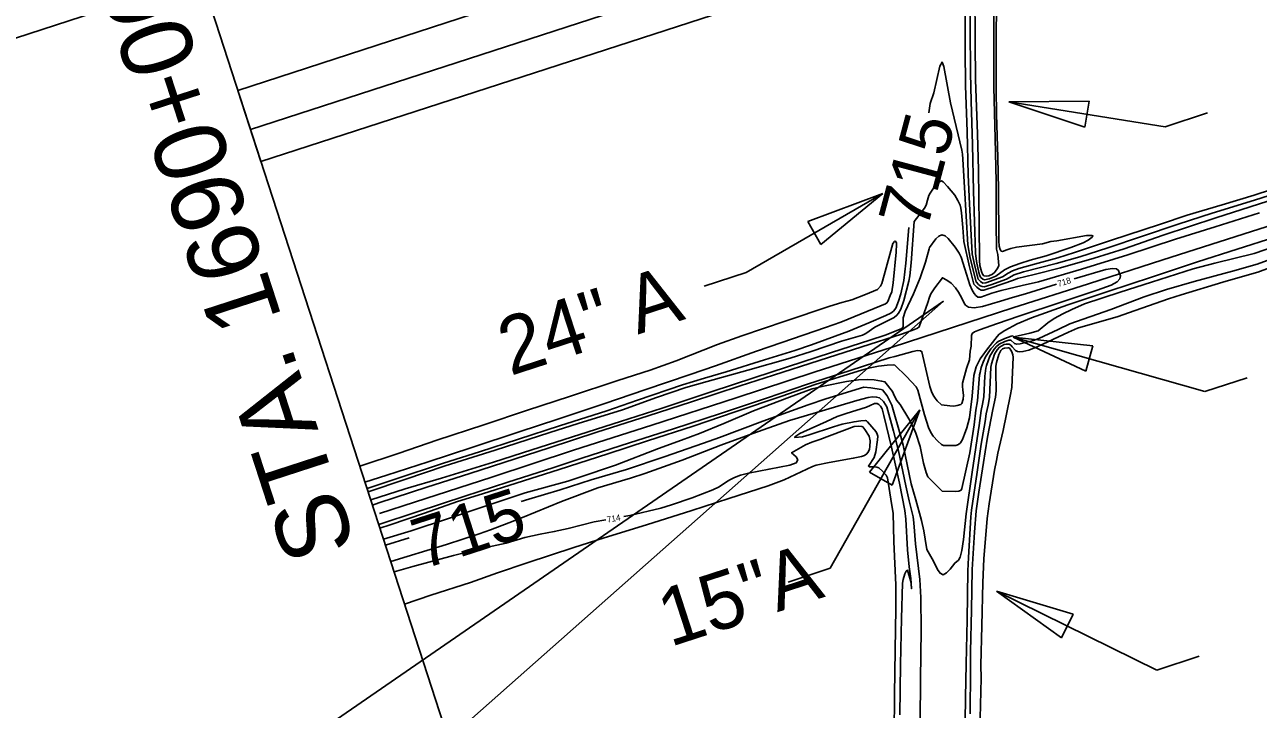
# Model space of a CAD drawing. Extents: x -468548933 to 3387700, y -306089263 to 1207014.
# Drawn here: x 1834585 to 1835390, y 535108 to 535554 of the extents above; entities that cross this region are included whole.
import ezdxf

# ---------------------------------------------------------------- set-up
doc = ezdxf.new("R2010")
doc.units = 0
for name, color, linetype in [('Default', 7, 'Continuous'), ('DT_X_Contour_Minor', 7, 'Continuous'), ('DT_X_Terrain_Ground_Line', 7, 'Continuous'), ('Level 14', 7, 'Continuous'), ('Level 19', 7, 'Continuous'), ('Level 40', 7, 'Continuous'), ('SC_Scratch1', 7, 'Continuous'), ('SC_Shading3', 7, 'Continuous')]:
    doc.layers.add(name, color=color, linetype=linetype)

msp = doc.modelspace()

# ---------------------------------------------------------------- linework, layer by layer
at = {"layer": 'Default'}
msp.add_lwpolyline([(1834724.08, 535511.25), (1834732.34, 535485.8), (1835112.79, 535609.32), (1835104.4, 535635.1)], close=True, dxfattribs=at)
at = {"layer": 'DT_X_Contour_Minor'}
for points in [[(1835219.01, 535568.51), (1835218.9, 535543.58), (1835218.75, 535511.83), (1835218.97, 535495.85), (1835219.96, 535467.46), (1835220.45, 535446.81), (1835220.55, 535413.17), (1835220.76, 535409.75), (1835221.36, 535407.54), (1835222.22, 535406.38), (1835222.92, 535406.29), (1835225.88, 535407.26), (1835228.49, 535408.13), (1835232.02, 535408.94), (1835249.12, 535411.22), (1835254.51, 535412.65), (1835258.36, 535413.13), (1835277.87, 535416.68), (1835281.17, 535416.67), (1835281.95, 535416.31), (1835281.53, 535415.56), (1835278.84, 535413.63), (1835275.71, 535411.95), (1835267.61, 535408.91), (1835251.5, 535403.43), (1835241.01, 535400.45), (1835234.26, 535398.36), (1835228.23, 535396.16), (1835224.27, 535394.14), (1835218.66, 535390.05), (1835214.19, 535388.35), (1835211.34, 535387.78), (1835210.22, 535388.06), (1835208.88, 535389.35), (1835208.26, 535390.39), (1835207.63, 535392.52), (1835206.03, 535399.61), (1835205.4, 535405.19), (1835205, 535418.92), (1835204.1, 535445.46), (1835203.46, 535476.08), (1835202.52, 535504.27), (1835202.03, 535522.72), (1835201.83, 535551.87), (1835201.89, 535578.71)], [(1835217.29, 535561.21), (1835217.32, 535530.19), (1835217.42, 535513.34), (1835218.19, 535479.94), (1835218.86, 535451.94), (1835218.82, 535424.79), (1835219.03, 535407.75), (1835219.96, 535404.24), (1835220.56, 535396.99), (1835220, 535395.63), (1835218.01, 535392.76), (1835216.48, 535391.36), (1835213.99, 535390.35), (1835212.48, 535390.14), (1835210.9, 535390.33), (1835209.98, 535391.45), (1835209.25, 535393.23), (1835208.3, 535397.02), (1835207.95, 535400.23), (1835207.72, 535423.53), (1835207.22, 535459.27), (1835206.58, 535483.02), (1835205.4, 535518.24), (1835205.08, 535542.71), (1835205.02, 535576.5)], [(1835198.58, 535568.22), (1835198.63, 535537.99), (1835198.86, 535514.32), (1835199.85, 535484.42), (1835200.64, 535456.13), (1835201.44, 535437.36), (1835203.24, 535404.69), (1835204.93, 535396.56), (1835207.13, 535388.14), (1835208.52, 535386.62), (1835210.21, 535385.55), (1835212.05, 535385.73), (1835222.94, 535389.63), (1835226.58, 535392.09), (1835229.42, 535393.53), (1835233.74, 535395.1), (1835243.81, 535398.03), (1835259.14, 535402.11), (1835269.97, 535405.49), (1835293.54, 535413.41), (1835326.12, 535424.12), (1835343.47, 535429.86), (1835366.35, 535436.68), (1835387.12, 535443), (1835410.39, 535450.48)], [(1835174.84, 535496.73), (1835175.68, 535502.77), (1835178.16, 535509.64), (1835182.11, 535527.01), (1835183.57, 535529.77), (1835184.8, 535526.92), (1835188.98, 535503.14), (1835196.34, 535472.21), (1835196.84, 535469.63), (1835197.16, 535466.36), (1835198.22, 535447.9), (1835200.29, 535410.47), (1835201.95, 535401.95), (1835205.71, 535386.48), (1835207.32, 535384.76), (1835208.41, 535383.88), (1835209.65, 535383.31), (1835210.96, 535383.26), (1835215.29, 535384.57), (1835225.6, 535388.22), (1835230.61, 535390.9), (1835236.7, 535392.86), (1835257.91, 535398.28), (1835273.39, 535402.75), (1835291.63, 535408.55), (1835313.67, 535415.88), (1835337.62, 535424.06), (1835359.7, 535431.19), (1835387.5, 535439.71), (1835416.71, 535449.08)], [(1834809.06, 535249.49), (1834832.96, 535257.62), (1834859.33, 535266.4), (1834891.93, 535276.68), (1834927.57, 535288.16), (1834946.17, 535293.95), (1834974.98, 535302.96), (1834997.14, 535310.89), (1835016.36, 535317.57), (1835030.2, 535321.45), (1835056.78, 535328.78), (1835084.45, 535336.59), (1835098.16, 535341.03), (1835117.95, 535347.63), (1835131.68, 535351.67), (1835133.75, 535352.66), (1835139.69, 535356.81), (1835152.4, 535363.26), (1835154.08, 535364.58), (1835155.22, 535365.9), (1835156.62, 535368.59), (1835158.58, 535374.34), (1835161.93, 535386.88), (1835162.62, 535390.37), (1835163.43, 535398.9), (1835165.29, 535425.68), (1835172.02, 535434.35), (1835173.14, 535436.39), (1835174.11, 535439.61), (1835174.94, 535442.75), (1835175.68, 535444.33), (1835178.05, 535447.4), (1835181.95, 535451.73), (1835183.15, 535452.21), (1835184.34, 535451.7), (1835187.02, 535448.65), (1835191.82, 535442.89), (1835193.9, 535439.38), (1835195.26, 535436.35), (1835195.82, 535434.4), (1835196.3, 535431.35), (1835197.05, 535421.92), (1835197.75, 535412.79), (1835201.55, 535396.11), (1835204.29, 535384.83), (1835206.13, 535382.9), (1835207.5, 535381.8), (1835209.1, 535381.06), (1835210.77, 535381), (1835213.5, 535381.86), (1835215.53, 535382.58), (1835230.25, 535387.55), (1835232.7, 535388.57), (1835243.58, 535391.22), (1835260.83, 535395.63), (1835282.7, 535401.89), (1835302.35, 535407.94), (1835327.8, 535416.75), (1835362.19, 535428.21), (1835384.67, 535435.36), (1835413.63, 535444.65)], [(1835390.57, 535431.45), (1835361.82, 535422.18), (1835335.79, 535414.18), (1835304.83, 535403.93), (1835274.63, 535394.71), (1835246.5, 535386.47), (1835235.76, 535383.99), (1835222.22, 535380.87), (1835215.96, 535378.98), (1835208.88, 535376.41), (1835206.87, 535376.32), (1835205.6, 535377.59), (1835204.58, 535378.84), (1835203.24, 535380.94), (1835201.67, 535384.4), (1835198.31, 535394.95), (1835196.03, 535402.54), (1835194.74, 535405.17), (1835192.08, 535409.12), (1835187.43, 535414.58), (1835185.53, 535416.32), (1835183.49, 535417.06), (1835181.44, 535416.25), (1835179.58, 535414.48), (1835175.41, 535408.9), (1835175.06, 535407.86), (1835172.67, 535399.3), (1835169.24, 535389.06), (1835164.94, 535378.54), (1835159.53, 535367.04), (1835158.25, 535362.98), (1835158.12, 535357.34), (1835157.76, 535356.38), (1835156.92, 535355.77), (1835146.37, 535351.75), (1835136.34, 535348.35), (1835111.47, 535340.36), (1835082.77, 535330.99), (1835060.79, 535323.86), (1835032.85, 535314.69), (1835000.91, 535304.12), (1834973.67, 535295.36), (1834947.31, 535286.89), (1834915.9, 535276.82), (1834890.89, 535268.91), (1834857.05, 535258.46), (1834833.24, 535251.39), (1834810.73, 535244.36)], [(1834808.39, 535251.55), (1834826.82, 535257.66), (1834858.3, 535268.21), (1834881.72, 535275.65), (1834907.29, 535283.83), (1834933.87, 535292.49), (1834964.88, 535302.26), (1834984.92, 535309.18), (1835014.18, 535319.35), (1835028.57, 535323.66), (1835042.77, 535327.72), (1835067.65, 535335.6), (1835087.55, 535341.54), (1835098.3, 535345.25), (1835122.75, 535354.28), (1835135.8, 535359.63), (1835146.83, 535364.42), (1835150.09, 535366.06), (1835151.84, 535367.24), (1835153.32, 535369.22), (1835155.2, 535373.92), (1835156.68, 535378.67), (1835158.57, 535387.31), (1835159.99, 535398.68), (1835161.82, 535421.94)], [(1834803.62, 535266.23), (1834829.3, 535274.61), (1834853.83, 535283.13), (1834884.47, 535293.22), (1834913.15, 535302.72), (1834940.38, 535311.58), (1834972.06, 535321.99), (1834993.1, 535328.87), (1835010.02, 535334.89), (1835037.09, 535345.6), (1835052.91, 535351.29), (1835081.2, 535360.67), (1835110.22, 535370.6), (1835118.06, 535372.9), (1835124.64, 535374.72), (1835133.62, 535378.11), (1835141.42, 535381.45), (1835143.48, 535383.61), (1835144.3, 535385.27), (1835145.88, 535390.8), (1835151.48, 535411.41), (1835152.56, 535412.82), (1835152.96, 535412.97), (1835153.28, 535412.72), (1835153.74, 535411.63), (1835153.87, 535410.99), (1835153.57, 535405.8), (1835151.63, 535385.82), (1835150.75, 535379.81), (1835149.78, 535377.5), (1835148.08, 535373.63), (1835147.58, 535372.66), (1835146.54, 535372.07), (1835139.35, 535369.05), (1835117.52, 535360.11), (1835107.51, 535356.54), (1835079, 535346.82), (1835062.54, 535341.25), (1835035.67, 535331.59), (1835019.16, 535326.06), (1834989.72, 535316.09), (1834963.57, 535307.18), (1834932.89, 535296.97), (1834907.71, 535288.6), (1834876.75, 535278.43), (1834848.15, 535269.06), (1834821.32, 535260.3), (1834807, 535255.83)], [(1835400.58, 535415.58), (1835376, 535407.7), (1835350.29, 535399.36), (1835320.93, 535389.77), (1835291.63, 535380.1), (1835265.64, 535371.35), (1835241.82, 535363.05), (1835232.6, 535358.94), (1835224.53, 535354.66), (1835220.81, 535352.38), (1835219.49, 535350.83), (1835214.89, 535344.8), (1835213.78, 535343.59), (1835208.41, 535336.16), (1835205.81, 535330.91), (1835204.29, 535325.4), (1835203.2, 535311.85), (1835201.4, 535297.82), (1835199.64, 535291.26), (1835198.29, 535287.07), (1835196.85, 535283.52), (1835195.5, 535281.37), (1835194.34, 535280.37), (1835192.54, 535279.76), (1835184.56, 535279.74), (1835183.14, 535280.31), (1835180.83, 535282.43), (1835177.75, 535285.77), (1835176.14, 535288.22), (1835174.7, 535291.38), (1835172.12, 535299.69), (1835167.82, 535315.83), (1835166.73, 535317.98), (1835160.25, 535324.65), (1835152.82, 535332.11)], [(1835400.37, 535409.56), (1835387.21, 535404.9), (1835361.48, 535398.62), (1835347.31, 535394.97), (1835320.2, 535386.27)], [(1835409.93, 535405.65), (1835389.2, 535398), (1835373.06, 535393.42), (1835347.98, 535386.62), (1835329.96, 535381.48), (1835315.51, 535376.56), (1835293.72, 535368.45), (1835266.91, 535359.02), (1835259.2, 535355.32), (1835246.76, 535349.41), (1835243.31, 535348.21), (1835234.47, 535345.93), (1835232.37, 535345.68), (1835230.84, 535346.12), (1835228.52, 535348.47), (1835227.06, 535348.39), (1835224.47, 535347.59), (1835220.91, 535345.83), (1835219.11, 535344.26), (1835217.47, 535342.43), (1835214.67, 535337.93), (1835212.45, 535331.78), (1835212.15, 535330.09), (1835211.66, 535326.54), (1835211.49, 535324.98), (1835210.79, 535311.4), (1835209.94, 535306.73), (1835209.11, 535302.41), (1835207.81, 535292.83), (1835207.06, 535288.69), (1835203.22, 535262.32), (1835199.21, 535235.22), (1835197.43, 535218.42), (1835196.4, 535211.28), (1835195.27, 535206.98), (1835194.19, 535204.96), (1835191.79, 535202.99), (1835188.79, 535199.11), (1835186.48, 535196.66), (1835184.19, 535195.46), (1835182.26, 535196.41), (1835180.65, 535198.86), (1835177.91, 535204.3), (1835173.64, 535211.98), (1835172.49, 535218.58), (1835171.55, 535224.12), (1835170.18, 535230.68), (1835166.41, 535244.36), (1835163.3, 535254.79), (1835158.13, 535279.88), (1835156.7, 535285.53), (1835150.79, 535306.09), (1835147.83, 535312.02), (1835144.58, 535315.89), (1835143.79, 535316.2), (1835137.15, 535317.23), (1835132.4, 535317.68), (1835107.81, 535310.08), (1835096.2, 535306.28), (1835066.64, 535295.56), (1835038.36, 535284.94), (1835027.85, 535281.16), (1835002.24, 535272.4), (1834977.68, 535264.04), (1834954.59, 535257.21), (1834934.3, 535250.76), (1834913.87, 535244.68), (1834909.03, 535243.18)], [(1835416.55, 535402.64), (1835389.63, 535392.83), (1835376.63, 535388.98), (1835366.72, 535386.18), (1835339.49, 535378.01), (1835331.28, 535375.36), (1835305.1, 535366.17), (1835298.42, 535363.88), (1835271.94, 535356.16), (1835266.06, 535353.57), (1835246.09, 535344.19), (1835240.18, 535341.84), (1835236.35, 535340.95), (1835234.13, 535340.81), (1835232.74, 535340.99), (1835231.42, 535341.6), (1835229.34, 535344.08), (1835228.37, 535345.2), (1835227.33, 535345.77), (1835225.49, 535345.85), (1835224.13, 535345.48), (1835221.01, 535343.79), (1835219.41, 535342.13), (1835217.77, 535339.25), (1835215.83, 535333.01), (1835215.35, 535330.74), (1835214.55, 535311.02), (1835213.57, 535306.04), (1835212.35, 535300.37), (1835211.71, 535295.26), (1835209.14, 535280.46)], [(1835269.7, 535388.29), (1835290.49, 535394.41), (1835294.8, 535395.17), (1835297.42, 535394.91), (1835298.71, 535393.82), (1835299.16, 535392.54)], [(1834811.85, 535240.89), (1834815.99, 535242.25), (1834847.32, 535252.46), (1834875.42, 535261.54), (1834897.52, 535268.6), (1834927.16, 535278.25), (1834958.37, 535288.29), (1834991.82, 535299.02), (1835020.08, 535308.16), (1835051.86, 535318.55), (1835073.62, 535325.59), (1835103.43, 535335.22), (1835131.14, 535343.95), (1835157.15, 535352.34), (1835165.48, 535355.23), (1835167.61, 535356.2), (1835168.51, 535357.06), (1835174.26, 535373), (1835175.29, 535376.43), (1835176.22, 535378.51), (1835178.91, 535382.51), (1835183.74, 535389.04), (1835186.61, 535387.46), (1835189.38, 535385.45), (1835192.32, 535382.57), (1835194.28, 535379.64), (1835196.51, 535375.69), (1835197.99, 535372.55), (1835198.91, 535371.2), (1835200.83, 535369.93), (1835204.43, 535369.51), (1835210.01, 535370.44), (1835221.57, 535373.83), (1835229.4, 535376.19), (1835237.91, 535378.66), (1835258.21, 535384.81)], [(1835299.16, 535392.54), (1835299.93, 535390.42), (1835299.63, 535388.45), (1835297.75, 535386.39), (1835293.86, 535384.31), (1835284.85, 535380.97), (1835261.84, 535373.46), (1835233.57, 535364.08), (1835219.81, 535359.25), (1835207.87, 535355.1), (1835204.62, 535353.71), (1835203.22, 535352.63), (1835202.86, 535351.47), (1835202.58, 535344.51), (1835201.98, 535341.27), (1835201.46, 535335.51), (1835199.45, 535329.92), (1835196.99, 535320.25), (1835196.78, 535318.33), (1835197.01, 535315.84), (1835197.59, 535312.55), (1835197.22, 535309.82), (1835196.39, 535307), (1835195.81, 535306.42), (1835193.48, 535305.71), (1835191.21, 535305.39), (1835188.54, 535305.51), (1835183.24, 535306.2), (1835180.31, 535308.91), (1835179.01, 535310.49), (1835177.82, 535312.43), (1835176.72, 535314.91), (1835175.65, 535318.15), (1835173.57, 535326.59), (1835170.37, 535340.82), (1835169.5, 535341.43), (1835167.61, 535341.54), (1835164.48, 535340.91), (1835152.83, 535337.82), (1835148.96, 535336.84), (1835123.62, 535328.66), (1835095.77, 535319.59), (1835068.92, 535310.6), (1835038.9, 535300.6), (1835008.29, 535290.62), (1834979.56, 535281.36), (1834948.54, 535271.33), (1834929.48, 535265.19), (1834900.27, 535255.68), (1834872.09, 535246.65), (1834841.1, 535236.41), (1834815.96, 535228.23)], [(1835320.2, 535386.27), (1835299.78, 535379.69), (1835276.47, 535372.01), (1835268.27, 535368.36), (1835262.27, 535365.48), (1835256.68, 535362.48), (1835252.62, 535359.79), (1835246.19, 535354.46), (1835240.79, 535353.01), (1835230.43, 535350.57), (1835230, 535350.97), (1835229.7, 535351.18), (1835228.62, 535350.93), (1835224.44, 535349.53), (1835220.18, 535347.43), (1835219.17, 535346.54), (1835215.42, 535342.7), (1835211.92, 535337.62), (1835210.36, 535334.08), (1835208.98, 535330.5), (1835208.31, 535327.36), (1835207.92, 535325.7), (1835206.61, 535308.8), (1835205.66, 535302.81), (1835204.45, 535293.1), (1835201.64, 535274.91), (1835196.53, 535251.7), (1835195.96, 535250.64), (1835194.58, 535250.02), (1835191.99, 535249.66), (1835183.54, 535249.95), (1835174.2, 535259.37), (1835173.1, 535262.03), (1835171.5, 535268.14), (1835169.22, 535279.04), (1835166.44, 535287.84), (1835165.19, 535290.81), (1835161.8, 535297.1), (1835156.14, 535306.33), (1835153.81, 535309.27), (1835151.91, 535313.48), (1835151.19, 535314.85), (1835146.24, 535321.31), (1835144.12, 535321.68), (1835139.29, 535322.47), (1835135, 535322.75), (1835128.97, 535322.47), (1835121.21, 535321.39), (1835106.29, 535318.47), (1835098.71, 535316.6), (1835084, 535311.22), (1835060.53, 535302.39), (1835041.11, 535294.09), (1835025.39, 535287.62), (1835013.49, 535283.16), (1834998.5, 535277.82), (1834970.58, 535266.96), (1834946.61, 535258.75), (1834939.47, 535256.42), (1834911.55, 535248.75), (1834906.23, 535247.13), (1834882.82, 535239.16), (1834861.53, 535231.99), (1834837.19, 535224.15), (1834819.07, 535218.66)], [(1835201.8, 535104.78), (1835202.13, 535133.31), (1835202.02, 535145.37), (1835202.65, 535172.42), (1835203.09, 535198.9), (1835204.71, 535223.28), (1835205.75, 535237.06), (1835207.5, 535249.33), (1835210.67, 535268.69), (1835211.71, 535275.61), (1835213.1, 535285.06), (1835216.68, 535303.17), (1835218.4, 535311.19), (1835218.94, 535315.31), (1835218.66, 535328.02), (1835218.58, 535331.38), (1835219.02, 535333.82), (1835220.62, 535339.01), (1835221.91, 535341.71), (1835222.9, 535342.64), (1835224.34, 535343.27), (1835226.49, 535343.49), (1835227.17, 535343.36), (1835227.86, 535342.87), (1835229.13, 535340.77), (1835229.82, 535338.78), (1835229.91, 535337.29), (1835229.05, 535317.49), (1835228.07, 535311.89), (1835223.48, 535289.4), (1835219.98, 535274.66)], [(1835152.82, 535332.11), (1835151.8, 535332.29), (1835147.83, 535332.17), (1835141.99, 535331.42), (1835135.65, 535330.08), (1835128.91, 535328.13), (1835100.81, 535319.47), (1835078.94, 535311.9), (1835048.66, 535301.61), (1835021.11, 535292.32), (1834991.41, 535282.74), (1834965.58, 535274.32), (1834933.81, 535264.01), (1834905.7, 535255.09), (1834883.6, 535248.2), (1834867.38, 535243.08), (1834845.85, 535235.53), (1834823.48, 535227.91), (1834816.77, 535225.74)], [(1835169.33, 535099.67), (1835169.55, 535127.31), (1835169.85, 535159.28), (1835169.59, 535180.6), (1835168.96, 535192.3), (1835166.17, 535215.57), (1835165.07, 535229.25), (1835164.63, 535233.17), (1835162.11, 535243.52), (1835159.86, 535253.41), (1835155.05, 535276.11), (1835151.88, 535288.94), (1835147.44, 535304.92), (1835145.39, 535308.34), (1835142.68, 535310.77), (1835140.87, 535311.3), (1835138.16, 535311.5), (1835135.29, 535311.1), (1835128.04, 535309.11), (1835105.4, 535302.33), (1835084.01, 535295.93), (1835060.1, 535287.59), (1835039.12, 535279.85), (1835013.99, 535270.18), (1834989.65, 535261.43), (1834980.31, 535258.39), (1834959.05, 535252.09), (1834935.17, 535243.11), (1834909.83, 535232.76), (1834900.89, 535229.29), (1834888.83, 535224.81), (1834881.61, 535222.18), (1834860.25, 535215.19), (1834834.44, 535207.33), (1834823.79, 535204.13)], [(1835152.19, 535091.28), (1835152.51, 535117.29), (1835152.92, 535146.27), (1835153.37, 535173.38), (1835153.36, 535188.78), (1835152.52, 535207.23), (1835152.17, 535217.04), (1835151.63, 535235.54), (1835150.58, 535241.9), (1835147.96, 535258.58), (1835147.02, 535260.35), (1835144.99, 535262.73), (1835142.24, 535265.09), (1835141.07, 535265.62), (1835138.7, 535265.69), (1835135.99, 535265.76), (1835135.54, 535266.24), (1835139.24, 535271.82), (1835140.37, 535275.65), (1835141.46, 535283.36), (1835141.57, 535285.68), (1835141.3, 535287.19), (1835140.49, 535288.59), (1835134.99, 535295.17), (1835134.34, 535295.78), (1835133.65, 535296.01), (1835130.62, 535295.76), (1835126.1, 535295.19), (1835118.28, 535293.62), (1835112.63, 535291.95), (1835096.79, 535286.55), (1835092.44, 535285.34), (1835087.38, 535285.01), (1835087.58, 535285.34), (1835090.81, 535287.44), (1835093.22, 535288.67), (1835108.1, 535295.4), (1835115.12, 535298.61), (1835121.07, 535300.55), (1835134.18, 535304.61), (1835136.72, 535305.77), (1835139.47, 535307.08), (1835141.26, 535307.05), (1835142.34, 535306.47), (1835143.34, 535305.45), (1835144.4, 535303.52), (1835145.63, 535299.18), (1835150.5, 535278.65), (1835155.78, 535255.1), (1835159.3, 535237.39), (1835159.81, 535231.7), (1835161.09, 535211.65), (1835162.12, 535200.52), (1835163.12, 535193.04), (1835163.69, 535186.25), (1835163.3, 535190.2), (1835161.08, 535198.32), (1835160.17, 535197.74), (1835159.26, 535195.91), (1835158.09, 535192.23), (1835157.8, 535189.87), (1835157.14, 535166.96), (1835156.39, 535136.83), (1835155.92, 535104)], [(1834975.91, 535233.3), (1834979.82, 535233.99), (1835000.06, 535238.8), (1835007.12, 535240.91), (1835020.55, 535245.63), (1835033.9, 535250.8), (1835038.16, 535252.82), (1835042.95, 535255.9), (1835045.18, 535257.37), (1835048.07, 535258.86), (1835052.01, 535260.33), (1835057.29, 535261.76), (1835070.73, 535264.37), (1835084.29, 535266.79), (1835088.36, 535268.32), (1835089.37, 535270.24), (1835088.35, 535272.21), (1835085.39, 535275.02), (1835094.42, 535280.12), (1835098.63, 535281.8), (1835103.75, 535283.5), (1835126.2, 535292.15), (1835128.9, 535292.36), (1835131.24, 535292.14), (1835131.82, 535291.77), (1835133.14, 535290.03), (1835135.94, 535285.71), (1835136.56, 535282.7), (1835136.52, 535279.13), (1835136.18, 535277.35), (1835135.5, 535275.72), (1835134.39, 535274.35), (1835132.86, 535273.26), (1835130.96, 535272.45), (1835125.56, 535271.34), (1835109.78, 535268.55), (1835101.44, 535266.85), (1835098.96, 535266.06), (1835091.56, 535262.59), (1835080.46, 535257.4), (1835070.17, 535253.46), (1835044.42, 535245.06), (1835020.18, 535237.26), (1834990.8, 535228.06), (1834963.17, 535219.4), (1834943.33, 535213.18), (1834912.8, 535203.08), (1834893.51, 535196.57), (1834875.78, 535190.45), (1834849.97, 535182.07), (1834832.82, 535176.31)], [(1835209.14, 535280.46), (1835206.36, 535262.38), (1835202.75, 535237.56), (1835202.42, 535233.26), (1835200.73, 535206.57), (1835200.42, 535197.92), (1835199.94, 535166.09), (1835199.32, 535137.4), (1835198.86, 535115.27), (1835198.45, 535084.58), (1835198.17, 535054.64), (1835197.93, 535026.34), (1835197.92, 535003.8), (1835197.93, 534973.08), (1835197.38, 534941.1), (1835197.38, 534941.06)], [(1835219.98, 535274.66), (1835219.05, 535269.88), (1835217.71, 535263.53), (1835214.25, 535241.65), (1835212.92, 535232.16), (1835210.89, 535205.73), (1835210.08, 535190.36), (1835209.53, 535162.03), (1835208.93, 535136.38), (1835208.97, 535127.88), (1835208.38, 535101.96), (1835207.84, 535084.84), (1835207.48, 535067.63), (1835207.29, 535057.87), (1835207.1, 535041.92), (1835205.71, 535015.18), (1835205.48, 534998.1), (1835205.43, 534981.54)], [(1834825.99, 535197.34), (1834838.3, 535200.75), (1834864.72, 535207.91), (1834876.76, 535211.08), (1834886.94, 535213.46), (1834899.11, 535216.08), (1834911.28, 535219.77), (1834921.31, 535221.8), (1834930.56, 535223.51), (1834939.55, 535225.63), (1834956.49, 535229.84), (1834964.1, 535231.19)], [(1834835.94, 535219.43), (1834820.39, 535214.6)]]:
    msp.add_lwpolyline(points, dxfattribs=at)
at = {"layer": 'DT_X_Terrain_Ground_Line'}
msp.add_line((1835055.83, 534489.39), (1834448.38, 536360.46), dxfattribs=at)
at = {"layer": 'Level 14'}
msp.add_lwpolyline([(1835432.68, 535434.33), (1835385.52, 535419.18), (1835327.6, 535400.75), (1835279.05, 535385.05), (1835229.63, 535369.46), (1835150.9, 535343.86), (1835100.03, 535327.48), (1835049.22, 535310.83), (1834994.2, 535292.97), (1834943.17, 535276.62), (1834889.77, 535259.14), (1834839.34, 535242.77), (1834816.44, 535235.31)], dxfattribs=at)
at = {"layer": 'Level 40'}
for p, q in [((1835227.15, 535503.89), (1835279.43, 535504.22)), ((1835329.15, 535487.59), (1835227.15, 535503.89)), ((1835276.72, 535487.26), (1835227.15, 535503.89)), ((1835279.43, 535504.22), (1835276.72, 535487.26)), ((1835329.15, 535487.59), (1835356.72, 535496.54)), ((1835055.78, 535392.56), (1835144.86, 535444.06)), ((1835095.91, 535425.69), (1835144.86, 535444.06)), ((1835144.86, 535444.06), (1835104.5, 535410.82)), ((1835104.5, 535410.82), (1835095.91, 535425.69)), ((1835028.22, 535383.61), (1835055.78, 535392.56)), ((1835355.01, 535314.95), (1835230.02, 535350.42)), ((1835277.29, 535328.07), (1835230.02, 535350.42)), ((1835230.02, 535350.42), (1835281.98, 535344.59)), ((1835281.98, 535344.59), (1835277.29, 535328.07)), ((1835355.01, 535314.95), (1835382.58, 535323.9)), ((1835110.6, 535199.61), (1835169.03, 535302.87)), ((1835136.15, 535262.22), (1835169.03, 535302.87)), ((1835169.03, 535302.87), (1835151.1, 535253.76)), ((1835151.1, 535253.76), (1835136.15, 535262.22)), ((1835083.04, 535190.66), (1835110.6, 535199.61)), ((1835323.64, 535133.3), (1835219.1, 535184.78)), ((1835261.58, 535154.28), (1835219.1, 535184.78)), ((1835219.1, 535184.78), (1835269.16, 535169.69)), ((1835269.16, 535169.69), (1835261.58, 535154.28)), ((1835323.64, 535133.3), (1835351.2, 535142.25))]:
    msp.add_line(p, q, dxfattribs=at)
for points in [[(1834648.53, 535567.95), (1834128.38, 535399.08), (1834064.25, 535596.62), (1834584.4, 535765.49)], [(1835184.4, 535373.82), (1834717.76, 535052.39), (1834740.81, 534981.41)]]:
    msp.add_lwpolyline(points, close=True, dxfattribs=at)
at = {"layer": 'SC_Scratch1'}
msp.add_lwpolyline([(1834448.38, 536360.46), (1835055.83, 534489.39), (1836664.2, 534206.16), (1839225.76, 534394.17), (1842361.7, 536308.3), (1842189.37, 536805.14), (1841581.79, 538676.58), (1840313.7, 539042.49), (1837357.67, 538260.17), (1834781.04, 538194.31), (1834403.13, 536496.43)], close=True, dxfattribs=at)
at = {"layer": 'SC_Shading3'}
msp.add_lwpolyline([(1834739.13, 535464.87), (1834724.08, 535511.25), (1835104.4, 535635.1), (1835119.61, 535588.39)], close=True, dxfattribs=at)

# ---------------------------------------------------------------- texts
at = {"layer": 'DT_X_Terrain_Ground_Line'}
msp.add_text('MATCH LINE                 STA. 1690+00', height=46.8, rotation=107.98637, dxfattribs=at).set_placement((1835009.73, 534572.14))
at = {"layer": 'Level 19'}
for s, height, rotation, p in [('715', 33, 75.00591, (1835173.54, 535419.37)), ('718', 4, 16.86215, (1835259.51, 535383.12)), ('715', 33, 17.87628, (1834844.41, 535198.75)), ('714', 4, 10.08979, (1834965.22, 535229.36))]:
    msp.add_text(s, height=height, rotation=rotation, dxfattribs=at).set_placement(p)
at = {"layer": 'Level 40'}
for s, p in [('24" A', (1834901.77, 535324.94)), ('15"A', (1835006.03, 535148.19))]:
    msp.add_text(s, height=37.5, rotation=17.9864, dxfattribs=at).set_placement(p)

doc.saveas('drawing.dxf')
